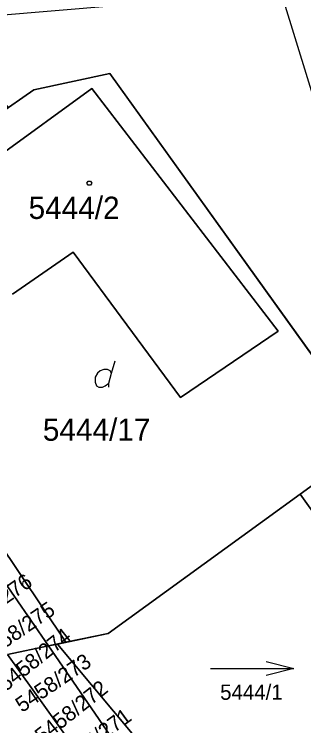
# Model space of a CAD drawing. Extents: x -263587 to -261993, y -1238795 to -1236748.
# Drawn here: x -262790.5 to -262769.7, y -1237202.8 to -1237151.7 of the extents above; entities that cross this region are included whole.
import ezdxf

# ---------------------------------------------------------------- set-up
doc = ezdxf.new("R2010")
doc.units = 0
doc.layers.add('Vrstva 1', color=7, linetype='Continuous')
doc.layers.add('Vrstva 3', color=7, linetype='Continuous')

msp = doc.modelspace()

# ---------------------------------------------------------------- linework, layer by layer
at = {"layer": 'Vrstva 1'}
for p, q in [((-262785.44, -1237103.96), (-262760.4, -1237185.76)), ((-262783.62, -1237155.92), (-262789.09, -1237157.1)), ((-262789.09, -1237157.1), (-262783.62, -1237155.92)), ((-262764.68, -1237182.32), (-262783.62, -1237155.92)), ((-262783.62, -1237155.92), (-262764.68, -1237182.32)), ((-262789.09, -1237157.1), (-262805.69, -1237168.66)), ((-262805.69, -1237168.66), (-262789.09, -1237157.1)), ((-262795.73, -1237164.84), (-262784.93, -1237157)), ((-262784.93, -1237157), (-262795.73, -1237164.84)), ((-262784.93, -1237157), (-262771.53, -1237174.45)), ((-262771.53, -1237174.45), (-262784.93, -1237157)), ((-262805.69, -1237168.66), (-262786.8, -1237196.8)), ((-262786.8, -1237196.8), (-262805.69, -1237168.66)), ((-262786.28, -1237168.77), (-262790.62, -1237171.78)), ((-262790.62, -1237171.78), (-262786.28, -1237168.77)), ((-262778.54, -1237179.21), (-262786.28, -1237168.77)), ((-262786.28, -1237168.77), (-262778.54, -1237179.21)), ((-262771.53, -1237174.45), (-262778.54, -1237179.21)), ((-262778.54, -1237179.21), (-262771.53, -1237174.45)), ((-262783.52, -1237177.47), (-262783.25, -1237176.57)), ((-262783.74, -1237196.16), (-262764.68, -1237182.32)), ((-262764.68, -1237182.32), (-262783.74, -1237196.16)), ((-262792.48, -1237190.65), (-262788.04, -1237197.06)), ((-262788.04, -1237197.06), (-262792.48, -1237190.65)), ((-262786.8, -1237196.8), (-262783.74, -1237196.16)), ((-262783.74, -1237196.16), (-262786.8, -1237196.8)), ((-262788.04, -1237197.06), (-262786.8, -1237196.8)), ((-262786.8, -1237196.8), (-262788.04, -1237197.06)), ((-262788.04, -1237197.06), (-262790.98, -1237197.67)), ((-262790.98, -1237197.67), (-262788.04, -1237197.06)), ((-262788.04, -1237197.06), (-262784.97, -1237201.5)), ((-262784.97, -1237201.5), (-262788.04, -1237197.06)), ((-262790.98, -1237197.67), (-262757.81, -1237244.02)), ((-262757.81, -1237244.02), (-262790.98, -1237197.67)), ((-262776.39, -1237198.68), (-262770.39, -1237198.68)), ((-262784.97, -1237201.5), (-262779.31, -1237209.74)), ((-262779.31, -1237209.74), (-262784.97, -1237201.5))]:
    msp.add_line(p, q, dxfattribs=at)
msp.add_lwpolyline([(-262785.01, -1237163.66), (-262784.92, -1237163.81), (-262785.01, -1237163.96), (-262785.19, -1237163.96), (-262785.28, -1237163.81), (-262785.19, -1237163.66)], close=True, dxfattribs=at)
for points in [[(-262783.7, -1237178.46), (-262783.7, -1237178.19), (-262783.52, -1237177.47), (-262783.61, -1237177.29), (-262783.79, -1237177.2), (-262784.06, -1237177.2), (-262784.33, -1237177.29), (-262784.51, -1237177.47), (-262784.69, -1237177.74), (-262784.69, -1237178.1), (-262784.6, -1237178.37), (-262784.42, -1237178.46), (-262784.15, -1237178.46), (-262783.97, -1237178.37), (-262783.7, -1237178.19)], [(-262772.39, -1237198.18), (-262770.39, -1237198.68), (-262772.39, -1237199.18)]]:
    msp.add_lwpolyline(points, dxfattribs=at)
at = {"layer": 'Vrstva 3'}
msp.add_lwpolyline([(-262749.008, -1237131.51), (-262742.07, -1237163.11), (-262732.76, -1237204.6), (-262726.59, -1237232.8), (-262723.9, -1237245.06), (-262720.535, -1237260.115), (-262727.51, -1237252.7), (-262744.25, -1237230.5), (-262748.29, -1237225.02), (-262749.81, -1237222.97), (-262759.86, -1237200.23), (-262769.952, -1237186.148), (-262764.68, -1237182.32), (-262783.62, -1237155.92), (-262789.09, -1237157.1), (-262790.929, -1237158.381), (-262795.88, -1237152.11), (-262774.99, -1237150.33)], dxfattribs=at)
for points in [[(-262748.29, -1237225.02), (-262743.43, -1237239.23), (-262744.55, -1237267.05), (-262745.66, -1237267.05), (-262745.71, -1237260.16), (-262752.03, -1237248.79), (-262749.8, -1237247.7), (-262753.21, -1237242.57), (-262774.08, -1237212.83), (-262787.389, -1237196.921), (-262783.74, -1237196.16), (-262769.952, -1237186.148), (-262759.86, -1237200.23), (-262749.81, -1237222.97)], [(-262787.389, -1237196.921), (-262774.08, -1237212.83), (-262753.21, -1237242.57), (-262755.03, -1237243.14), (-262755.84, -1237242), (-262757.56, -1237239.64), (-262763.18, -1237232.58), (-262767.47, -1237226.83), (-262774.92, -1237216.2), (-262779.31, -1237209.74), (-262784.97, -1237201.5), (-262788.04, -1237197.06)]]:
    msp.add_lwpolyline(points, close=True, dxfattribs=at)

# ---------------------------------------------------------------- texts
at = {"layer": 'Vrstva 1'}
for s, height, p in [('5444/2', 1.6, (-262789.473, -1237166.38)), ('5444/17', 1.6, (-262788.448, -1237182.32)), ('5444/1', 1.1, (-262775.698, -1237200.93))]:
    msp.add_text(s, height=height, dxfattribs=at).set_placement(p)
for s, rotation, p in [('5458/276', 34.9504, (-262794.132, -1237196.205)), ('5458/275', 34.4348, (-262792.525, -1237198.175)), ('5458/274', 38.5028, (-262791.111, -1237200.366)), ('5458/273', 34.091, (-262789.943, -1237201.879)), ('5458/272', 38.3309, (-262788.48, -1237204.109)), ('5458/271', 36.0963, (-262786.93, -1237205.96))]:
    msp.add_text(s, height=1.1, rotation=rotation, dxfattribs=at).set_placement(p)

doc.saveas('drawing.dxf')
